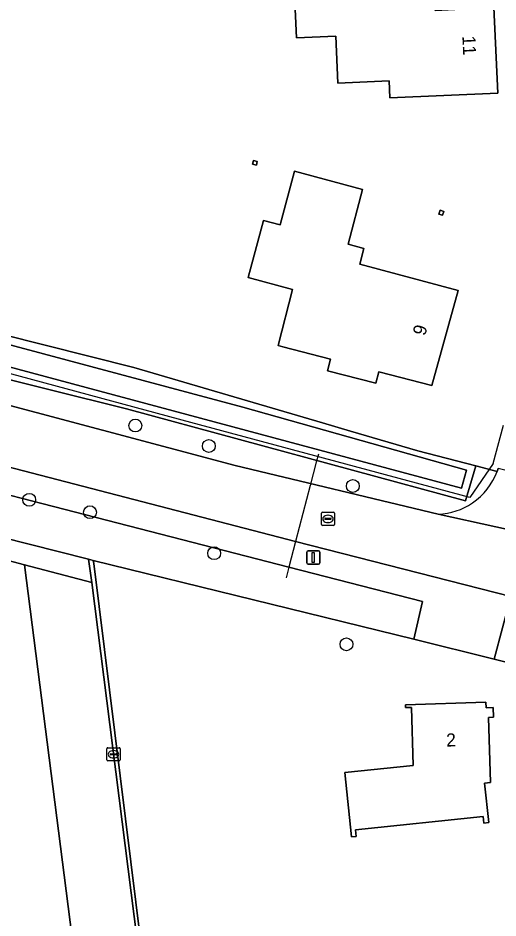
# Model space of a CAD drawing. Extents: x 162156 to 163172, y 378995 to 380779.
# Drawn here: x 162225.6 to 162262.1, y 380168.4 to 380236.9 of the extents above; entities that cross this region are included whole.
import ezdxf

# ---------------------------------------------------------------- set-up
doc = ezdxf.new("R2010")
doc.units = 0
for name, color, linetype in [('IMGEO_Boom', 7, 'Continuous'), ('IMGEO_Duiker', 7, 'Continuous'), ('IMGEO_Erf', 7, 'Continuous'), ('IMGEO_Groenvoorziening', 7, 'Continuous'), ('IMGEO_Hek', 7, 'Continuous'), ('IMGEO_Kolk', 7, 'Continuous'), ('IMGEO_Lichtmast', 7, 'Continuous'), ('IMGEO_Oever', 7, 'Continuous'), ('IMGEO_Pand', 7, 'Continuous'), ('IMGEO_Pand_nummerreeks', 7, 'Continuous'), ('IMGEO_Parkeervlak_gesloten', 7, 'Continuous'), ('IMGEO_Rijbaan_lokaal_gesloten', 7, 'Continuous'), ('IMGEO_Rijbaan_lokaal_open', 7, 'Continuous'), ('IMGEO_Rioolput', 7, 'Continuous'), ('IMGEO_Voetpad_open', 7, 'Continuous'), ('IMGEO_Waterloop', 7, 'Continuous')]:
    doc.layers.add(name, color=color, linetype=linetype)

msp = doc.modelspace()

# ---------------------------------------------------------------- linework, layer by layer
at = {"layer": 'IMGEO_Boom'}
for centre in [(162234.514, 380205.894), (162240.112, 380204.333), (162251.08, 380201.286), (162226.426, 380200.236), (162231.05, 380199.29), (162240.513, 380196.164), (162250.592, 380189.228)]:
    msp.add_circle(centre, 0.489, dxfattribs=at)
at = {"layer": 'IMGEO_Duiker'}
msp.add_lwpolyline([(162248.458, 380203.718), (162248.299, 380203.107), (162247.836, 380201.331), (162246.724, 380197.067), (162246.214, 380195.112), (162246.001, 380194.294)], dxfattribs=at)
at = {"layer": 'IMGEO_Erf'}
for points in [[(162246.476, 380242.067), (162252.244, 380242.346), (162252.314, 380240.403), (162254.103, 380240.493), (162254.159, 380239.392), (162257.251, 380239.541), (162257.348, 380237.528), (162261.822, 380237.739), (162262.124, 380231.229), (162253.902, 380230.849), (162253.842, 380232.147), (162249.946, 380231.967), (162249.78, 380235.563), (162246.783, 380235.425)], [(162243.798, 380226.018), (162243.732, 380225.723), (162243.441, 380225.802), (162243.517, 380226.092)], [(162251.816, 380223.865), (162250.731, 380219.711), (162251.926, 380219.392), (162251.602, 380218.195), (162259.113, 380216.177), (162257.101, 380208.949), (162253.056, 380209.995), (162252.823, 380209.118), (162249.148, 380210.071), (162249.377, 380210.957), (162245.746, 380211.892), (162245.391, 380211.984), (162246.495, 380216.264), (162243.106, 380217.181), (162244.281, 380221.525), (162245.536, 380221.185), (162246.641, 380225.268)], [(162257.724, 380222.296), (162258.01, 380222.208), (162257.923, 380221.921), (162257.636, 380222.009)], [(162278.772, 380184.135), (162278.442, 380184.1), (162277.89, 380189.107), (162274.745, 380189.91), (162275.3, 380184.768), (162265.85, 380187.096), (162261.843, 380188.084), (162255.724, 380189.614), (162231.309, 380195.607), (162231.337, 380195.38), (162235.369, 380163.029), (162235.526, 380161.77), (162280.517, 380167.715)], [(162261.57, 380178.695), (162261.12, 380178.649), (162261.433, 380175.641), (162261.062, 380175.602), (162261.01, 380176.101), (162251.289, 380175.09), (162251.342, 380174.585), (162250.973, 380174.547), (162250.463, 380179.453), (162255.687, 380179.996), (162255.543, 380184.421), (162255.09, 380184.406), (162255.084, 380184.609), (162261.216, 380184.807), (162261.229, 380184.386), (162261.768, 380184.403), (162261.792, 380183.666), (162261.409, 380183.654)]]:
    msp.add_lwpolyline(points, close=True, dxfattribs=at)
msp.add_lwpolyline([(162211.037, 380224.077), (162212.191, 380221.758), (162209.83, 380220.583), (162210.565, 380216.608), (162210.488, 380216.162), (162210.385, 380215.565), (162210.605, 380215.503), (162210.69, 380216.294), (162234.408, 380210.305), (162248.758, 380206.096), (162250.906, 380205.466), (162256.032, 380203.963), (162260.463, 380202.82), (162262.082, 380202.403), (162262.154, 380202.611)], dxfattribs=at)
at = {"layer": 'IMGEO_Groenvoorziening'}
for points in [[(162233.844, 380207.176), (162210.337, 380213.011), (162210.427, 380213.842), (162210.11, 380213.932), (162210.02, 380213.446), (162209.697, 380211.57), (162211.76, 380210.925), (162242.127, 380202.849), (162257.586, 380199.133)], [(162262.082, 380202.403), (162260.463, 380202.82), (162259.664, 380200.145), (162233.844, 380207.176)], [(162204.597, 380205.81), (162246.214, 380195.112), (162256.379, 380192.499), (162255.724, 380189.614), (162261.843, 380188.084), (162263.126, 380192.878), (162246.724, 380197.067), (162211.704, 380206.157)], [(162206.506, 380194.862), (162220.952, 380196.618), (162226.072, 380195.282), (162231.193, 380193.946), (162230.935, 380195.702), (162204.193, 380202.475)]]:
    msp.add_lwpolyline(points, dxfattribs=at)
msp.add_lwpolyline([(162231.337, 380195.38), (162231.309, 380195.607), (162230.935, 380195.702), (162231.193, 380193.946), (162235.101, 380163.068), (162235.109, 380163.008), (162235.369, 380163.029)], close=True, dxfattribs=at)
for centre, start, end in [((162257.366, 380204.163), 304.2105, 339.53614), ((162257.365, 380204.162), 272.52153, 304.22978)]:
    msp.add_arc(centre, 5.034, start, end, dxfattribs=at)
at = {"layer": 'IMGEO_Hek'}
for points in [[(162261.779, 380202.993), (162259.985, 380200.407), (162238.727, 380206.115), (162210.224, 380213.81)], [(162261.779, 380202.993), (162262.552, 380205.925)], [(162231.309, 380195.607), (162230.935, 380195.702), (162204.193, 380202.475)], [(162255.724, 380189.614), (162231.309, 380195.607)], [(162231.337, 380195.38), (162231.309, 380195.607)], [(162235.369, 380163.029), (162231.337, 380195.38)], [(162261.843, 380188.084), (162255.724, 380189.614)], [(162265.85, 380187.096), (162261.843, 380188.084)]]:
    msp.add_lwpolyline(points, dxfattribs=at)
at = {"layer": 'IMGEO_Kolk'}
for p, q in [((162232.348, 380180.422), (162232.348, 380181.274)), ((162232.423, 380181.348), (162233.275, 380181.348)), ((162232.65, 380180.891), (162233.048, 380180.891)), ((162232.836, 380181.128), (162232.861, 380181.128)), ((162233.349, 380181.274), (162233.349, 380180.422)), ((162233.275, 380180.348), (162232.423, 380180.348)), ((162232.607, 380180.842), (162232.607, 380180.854)), ((162233.045, 380180.805), (162232.647, 380180.805)), ((162232.859, 380180.568), (162232.834, 380180.568)), ((162233.091, 380180.854), (162233.091, 380180.842))]:
    msp.add_line(p, q, dxfattribs=at)
for points in [[(162232.348, 380180.422), (162232.348, 380181.274)], [(162232.423, 380181.348), (162233.275, 380181.348)], [(162233.349, 380181.274), (162233.349, 380180.422)], [(162233.275, 380180.348), (162232.423, 380180.348)]]:
    msp.add_lwpolyline(points, dxfattribs=at)
for centre, radius, start, end in [((162232.425, 380181.272), 0.0765, 91.55205, 178.44795), ((162232.425, 380181.272), 0.0765, 91.55205, 178.44795), ((162232.647, 380180.851), 0.0403, 85.87752, 175.75265), ((162233.052, 380180.853), 0.0386, 1.73085, 96.63898), ((162233.273, 380181.272), 0.0765, 1.55205, 88.44795), ((162233.273, 380181.272), 0.0765, 1.55205, 88.44795), ((162232.425, 380180.424), 0.0765, 181.55205, 268.44795), ((162232.425, 380180.424), 0.0765, 181.55205, 268.44795), ((162232.644, 380180.841), 0.0366, 178.93798, 274.71019), ((162233.048, 380180.848), 0.043, 264.86636, 352.45326), ((162233.273, 380180.424), 0.0765, 271.55205, 358.44795), ((162233.273, 380180.424), 0.0765, 271.55205, 358.44795)]:
    msp.add_arc(centre, radius, start, end, dxfattribs=at)
for centre, major_axis, ratio, start_param, end_param in [((162232.835, 380180.848), (-0.387, 0.002), 0.722429, 4.712389, 7.853982), ((162232.86, 380180.848), (-0.39, 0.002), 0.717154, 1.570796, 4.712389)]:
    msp.add_ellipse(centre, major_axis=major_axis, ratio=ratio, start_param=start_param, end_param=end_param, dxfattribs=at)
at = {"layer": 'IMGEO_Lichtmast'}
for p, q in [((162247.572, 380195.439), (162247.572, 380196.239)), ((162247.572, 380196.239), (162247.572, 380195.439)), ((162247.672, 380196.339), (162248.462, 380196.339)), ((162248.462, 380196.339), (162247.672, 380196.339)), ((162248.562, 380196.239), (162248.562, 380195.439)), ((162248.562, 380195.439), (162248.562, 380196.239)), ((162248.462, 380195.339), (162247.672, 380195.339)), ((162247.672, 380195.339), (162248.462, 380195.339))]:
    msp.add_line(p, q, dxfattribs=at)
msp.add_lwpolyline([(162247.992, 380196.214), (162248.142, 380196.214), (162248.142, 380195.464), (162247.992, 380195.464), (162247.992, 380196.214)], dxfattribs=at)
for centre, start, end in [((162247.672, 380196.239), 90, 180), ((162247.672, 380196.239), 90, 180), ((162248.462, 380196.239), 0, 90), ((162248.462, 380196.239), 360, 90), ((162247.672, 380195.439), 180, 270), ((162247.672, 380195.439), 180, 270), ((162248.462, 380195.439), 270, 0), ((162248.462, 380195.439), 270, 0)]:
    msp.add_arc(centre, 0.1, start, end, dxfattribs=at)
at = {"layer": 'IMGEO_Oever'}
for points in [[(162210.69, 380216.294), (162210.605, 380215.503), (162213.743, 380214.614), (162213.967, 380214.551), (162213.518, 380212.967), (162210.427, 380213.842), (162210.337, 380213.011), (162233.844, 380207.176), (162259.664, 380200.145), (162260.463, 380202.82), (162256.032, 380203.963), (162250.906, 380205.466), (162248.758, 380206.096), (162234.408, 380210.305)], [(162229.722, 380209.062), (162215.494, 380212.875), (162215.921, 380214.468), (162242.692, 380207.294), (162259.733, 380202.483), (162259.368, 380201.119)]]:
    msp.add_lwpolyline(points, close=True, dxfattribs=at)
at = {"layer": 'IMGEO_Pand'}
for points in [[(162246.476, 380242.067), (162246.783, 380235.425), (162249.78, 380235.563), (162249.946, 380231.967), (162253.842, 380232.147), (162253.902, 380230.849), (162262.124, 380231.229), (162261.822, 380237.739), (162257.348, 380237.528), (162257.251, 380239.541), (162254.159, 380239.392), (162254.103, 380240.493), (162252.314, 380240.403), (162252.244, 380242.346)], [(162243.517, 380226.092), (162243.441, 380225.802), (162243.732, 380225.723), (162243.798, 380226.018)], [(162251.816, 380223.865), (162246.641, 380225.268), (162245.536, 380221.185), (162244.281, 380221.525), (162243.106, 380217.181), (162246.495, 380216.264), (162245.391, 380211.984), (162245.746, 380211.892), (162249.377, 380210.957), (162249.148, 380210.071), (162252.823, 380209.118), (162253.056, 380209.995), (162257.101, 380208.949), (162259.113, 380216.177), (162251.602, 380218.195), (162251.926, 380219.392), (162250.731, 380219.711)], [(162257.724, 380222.296), (162257.636, 380222.009), (162257.923, 380221.921), (162258.01, 380222.208)], [(162250.973, 380174.547), (162251.342, 380174.585), (162251.289, 380175.09), (162261.01, 380176.101), (162261.062, 380175.602), (162261.433, 380175.641), (162261.12, 380178.649), (162261.57, 380178.695), (162261.409, 380183.654), (162261.792, 380183.666), (162261.768, 380184.403), (162261.229, 380184.386), (162261.216, 380184.807), (162255.084, 380184.609), (162255.09, 380184.406), (162255.543, 380184.421), (162255.687, 380179.996), (162250.463, 380179.453)]]:
    msp.add_lwpolyline(points, close=True, dxfattribs=at)
at = {"layer": 'IMGEO_Parkeervlak_gesloten'}
msp.add_lwpolyline([(162231.193, 380193.946), (162226.072, 380195.282), (162230.258, 380162.505), (162230.905, 380162.587), (162235.109, 380163.008), (162235.101, 380163.068)], close=True, dxfattribs=at)
at = {"layer": 'IMGEO_Rijbaan_lokaal_gesloten'}
for points in [[(162295.129, 380190.42), (162294.603, 380190.539), (162270.767, 380196.252), (162257.586, 380199.133), (162242.127, 380202.849), (162211.76, 380210.925), (162209.697, 380211.57), (162201.813, 380214.036), (162199.997, 380214.604), (162197.517, 380215.45), (162195.952, 380211.32), (162198.831, 380210.194)], [(162206.351, 380207.122), (162208.869, 380206.76), (162209.36, 380206.69), (162211.704, 380206.157), (162246.724, 380197.067), (162263.126, 380192.878), (162267.042, 380191.877), (162274.745, 380189.91), (162277.89, 380189.107), (162289.203, 380186.217)], [(162222.649, 380166.325), (162223.175, 380161.606), (162226.536, 380162.031), (162230.258, 380162.505), (162226.072, 380195.282), (162220.952, 380196.618), (162206.506, 380194.862)]]:
    msp.add_lwpolyline(points, dxfattribs=at)
at = {"layer": 'IMGEO_Rijbaan_lokaal_open'}
for points in [[(162273.297, 380236.316), (162264.125, 380202.118), (162263.688, 380202.236), (162262.154, 380202.611), (162262.082, 380202.403)], [(162257.586, 380199.133), (162270.767, 380196.252)]]:
    msp.add_lwpolyline(points, dxfattribs=at)
for centre, start, end in [((162257.366, 380204.163), 304.2105, 339.53614), ((162257.365, 380204.162), 272.52153, 304.22978)]:
    msp.add_arc(centre, 5.034, start, end, dxfattribs=at)
at = {"layer": 'IMGEO_Rioolput'}
for p, q in [((162248.685, 380198.356), (162248.685, 380199.208)), ((162248.76, 380199.282), (162249.612, 380199.282)), ((162248.944, 380198.776), (162248.944, 380198.788)), ((162249.382, 380198.739), (162248.984, 380198.739)), ((162248.987, 380198.825), (162249.385, 380198.825)), ((162249.173, 380199.062), (162249.198, 380199.062)), ((162249.428, 380198.788), (162249.428, 380198.776)), ((162249.686, 380199.208), (162249.686, 380198.356)), ((162249.612, 380198.282), (162248.76, 380198.282)), ((162249.196, 380198.502), (162249.171, 380198.502))]:
    msp.add_line(p, q, dxfattribs=at)
for points in [[(162248.685, 380198.356), (162248.685, 380199.208)], [(162248.76, 380199.282), (162249.612, 380199.282)], [(162249.686, 380199.208), (162249.686, 380198.356)], [(162249.612, 380198.282), (162248.76, 380198.282)]]:
    msp.add_lwpolyline(points, dxfattribs=at)
for centre, radius, start, end in [((162248.762, 380199.206), 0.0765, 91.55205, 178.44795), ((162248.762, 380199.206), 0.0765, 91.55205, 178.44795), ((162248.984, 380198.785), 0.0403, 85.87752, 175.75265), ((162248.981, 380198.775), 0.0366, 178.93798, 274.71019), ((162249.385, 380198.782), 0.043, 264.86636, 352.45326), ((162249.389, 380198.787), 0.0386, 1.73085, 96.63898), ((162249.61, 380199.206), 0.0765, 1.55205, 88.44795), ((162249.61, 380199.206), 0.0765, 1.55205, 88.44795), ((162248.762, 380198.358), 0.0765, 181.55205, 268.44795), ((162248.762, 380198.358), 0.0765, 181.55205, 268.44795), ((162249.61, 380198.358), 0.0765, 271.55205, 358.44795), ((162249.61, 380198.358), 0.0765, 271.55205, 358.44795)]:
    msp.add_arc(centre, radius, start, end, dxfattribs=at)
for centre, major_axis, ratio, start_param, end_param in [((162249.172, 380198.782), (-0.387, 0.002), 0.722429, 4.712389, 7.853982), ((162249.197, 380198.782), (-0.39, 0.002), 0.717154, 1.570796, 4.712389)]:
    msp.add_ellipse(centre, major_axis=major_axis, ratio=ratio, start_param=start_param, end_param=end_param, dxfattribs=at)
at = {"layer": 'IMGEO_Voetpad_open'}
msp.add_lwpolyline([(162267.042, 380191.877), (162263.126, 380192.878), (162261.843, 380188.084), (162265.85, 380187.096), (162265.974, 380187.592), (162266.54, 380189.863)], close=True, dxfattribs=at)
at = {"layer": 'IMGEO_Waterloop'}
msp.add_lwpolyline([(162259.733, 380202.483), (162242.692, 380207.294), (162215.921, 380214.468), (162215.494, 380212.875), (162229.722, 380209.062), (162259.368, 380201.119)], close=True, dxfattribs=at)
msp.add_lwpolyline([(162204.557, 380205.565), (162204.265, 380204.234), (162203.952, 380202.622), (162204.193, 380202.475), (162230.935, 380195.702), (162231.309, 380195.607), (162255.724, 380189.614), (162256.379, 380192.499), (162246.214, 380195.112), (162204.597, 380205.81)], dxfattribs=at)

# ---------------------------------------------------------------- texts
at = {"layer": 'IMGEO_Pand_nummerreeks'}
for s, rotation, p in [('11', 272.65831, (162259.42, 380235.576)), ('9', 74.44441, (162256.583, 380212.683)), ('2', 1.84942, (162258.205, 380181.429))]:
    msp.add_text(s, height=1, rotation=rotation, dxfattribs=at).set_placement(p)

doc.saveas('drawing.dxf')
